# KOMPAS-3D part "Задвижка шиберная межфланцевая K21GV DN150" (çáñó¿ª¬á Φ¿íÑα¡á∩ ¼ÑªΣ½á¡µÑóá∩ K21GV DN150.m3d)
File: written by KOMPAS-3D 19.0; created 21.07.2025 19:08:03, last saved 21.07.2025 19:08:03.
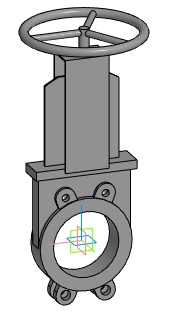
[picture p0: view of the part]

Document properties: Автор: Евгений; Полное имя файла: E:\Dendor Работа Сачек\3D для проектировщиков\2.3 Тип K21GV. Задвижка шиберная межфланцевая\stp_Задвижка шиберная K21GV DN50-400 с маховиком\Задвижка шиберная межфланцевая K21GV DN150.m3d

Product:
- Part/product: Задвижка шиберная межфланцевая K21GV DN150

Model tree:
1. Операция без истории:1  (labels: Задвижка шиберная межфланцевая K21GV DN150)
